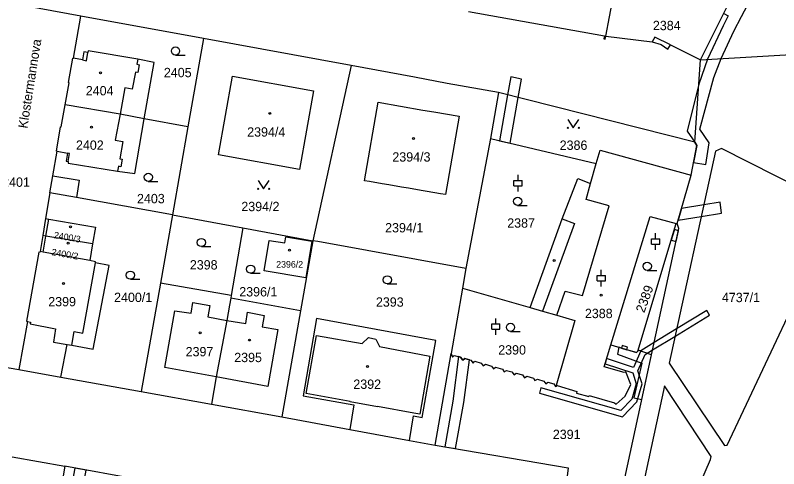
# Model space of a CAD drawing. Extents: x -756746 to -753363, y -1166406 to -1161727.
# Drawn here: x -755962.9 to -755823.6, y -1164823.5 to -1164740.9 of the extents above; entities that cross this region are included whole.
import ezdxf

# ---------------------------------------------------------------- set-up
doc = ezdxf.new("R2010")
doc.units = 0
for name, color, linetype in [('Hranice parcel', 7, 'Continuous'), ('Parcelní čísla', 7, 'Continuous'), ('Pop  PČ popisy', 7, 'Continuous'), ('Vnitřní kresba', 7, 'Continuous'), ('Věcná břemena k části', 7, 'Continuous'), ('Značky budov', 7, 'Continuous'), ('Značky kultur', 7, 'Continuous')]:
    doc.layers.add(name, color=color, linetype=linetype)

msp = doc.modelspace()

# ---------------------------------------------------------------- linework, layer by layer
at = {"layer": 'Hranice parcel'}
for p, q in [((-755855.19, -1164744.66), (-755853.26, -1164734.57)), ((-755950.9, -1164741.05), (-755966.59, -1164738.18)), ((-755837.91, -1164748.96), (-755832.95, -1164739.17)), ((-755952.27, -1164748.71), (-755950.9, -1164741.05)), ((-755928.54, -1164745.07), (-755950.9, -1164741.05)), ((-755928.54, -1164745.07), (-755931.39, -1164761.17)), ((-755901.64, -1164750.02), (-755928.54, -1164745.07)), ((-755837.91, -1164748.96), (-755819.27, -1164747.92)), ((-755838.9, -1164764), (-755837.91, -1164748.96)), ((-755901.64, -1164750.02), (-755908.6, -1164781.97)), ((-755874.74, -1164754.96), (-755876.22, -1164763.34)), ((-755838.9, -1164764), (-755874.74, -1164754.96)), ((-755888.54, -1164758.13), (-755886.52, -1164758.48)), ((-755931.39, -1164761.17), (-755939.37, -1164759.72)), ((-755931.39, -1164761.17), (-755934.2, -1164777.22)), ((-755876.22, -1164763.34), (-755880.7, -1164787.03)), ((-755876.22, -1164763.34), (-755856.91, -1164767.9)), ((-755842.15, -1164778.83), (-755839.59, -1164770)), ((-755956.59, -1164773.21), (-755957.36, -1164777.9)), ((-755957.36, -1164777.9), (-755957.88, -1164780.99)), ((-755934.2, -1164777.22), (-755936.42, -1164789.71)), ((-755934.2, -1164777.22), (-755921.38, -1164779.59)), ((-755921.38, -1164779.59), (-755923.5, -1164791.94)), ((-755921.38, -1164779.59), (-755908.6, -1164781.97)), ((-755842.31, -1164778.79), (-755842.15, -1164778.83)), ((-755957.88, -1164780.99), (-755958.36, -1164783.93)), ((-755948.79, -1164782.53), (-755949.31, -1164785.58)), ((-755908.6, -1164781.97), (-755910.86, -1164794.7)), ((-755880.7, -1164787.03), (-755881.32, -1164790.59)), ((-755936.42, -1164789.71), (-755939.91, -1164809.4)), ((-755923.5, -1164791.94), (-755936.42, -1164789.71)), ((-755881.32, -1164790.59), (-755883.39, -1164802.48)), ((-755881.32, -1164790.59), (-755868.99, -1164794.14)), ((-755923.5, -1164791.94), (-755923.57, -1164792.39)), ((-755910.86, -1164794.7), (-755923.57, -1164792.39)), ((-755910.86, -1164794.7), (-755914.29, -1164814.02)), ((-755977.93, -1164802.62), (-755962.23, -1164805.42)), ((-755886.32, -1164819.18), (-755883.39, -1164802.48)), ((-755962.23, -1164805.42), (-755954.58, -1164806.78)), ((-755954.58, -1164806.78), (-755939.91, -1164809.4)), ((-755939.91, -1164809.4), (-755927.1, -1164811.72)), ((-755927.1, -1164811.72), (-755914.29, -1164814.02)), ((-755914.29, -1164814.02), (-755901.84, -1164816.32)), ((-755901.84, -1164816.32), (-755890.99, -1164818.32)), ((-755890.99, -1164818.32), (-755886.32, -1164819.18)), ((-755963.43, -1164821.33), (-755953.82, -1164823.05)), ((-755940.53, -1164825.47), (-755953.82, -1164823.05))]:
    msp.add_line(p, q, dxfattribs=at)
for points in [[(-755880.19, -1164740.17), (-755855.43, -1164744.63), (-755855.53, -1164745.18), (-755855.29, -1164745.22), (-755855.19, -1164744.66)], [(-755855.19, -1164744.66), (-755846.72, -1164745.69), (-755845.05, -1164746.17), (-755843.84, -1164747.05), (-755843.37, -1164746.27), (-755837.91, -1164748.96)], [(-755939.37, -1164759.72), (-755937.52, -1164749.46), (-755940.54, -1164748.89), (-755949.59, -1164747.36), (-755949.64, -1164747.65), (-755950.39, -1164747.51), (-755950.65, -1164749), (-755952.27, -1164748.71)], [(-755953.8, -1164757.17), (-755953.06, -1164753.15), (-755953.16, -1164753.13), (-755952.37, -1164748.69), (-755952.27, -1164748.71)], [(-755874.74, -1164754.96), (-755884.11, -1164753.28), (-755890.07, -1164752.16), (-755901.64, -1164750.02)], [(-755925.84, -1164766.28), (-755923.24, -1164751.99), (-755908.46, -1164754.66), (-755911.06, -1164768.95), (-755925.84, -1164766.28)], [(-755955.26, -1164765.63), (-755955.36, -1164765.61), (-755954.63, -1164761.18), (-755954.53, -1164761.2), (-755953.8, -1164757.17)], [(-755939.37, -1164759.72), (-755943.78, -1164758.87), (-755953.8, -1164757.17)], [(-755898.27, -1164771.18), (-755899.18, -1164771.02), (-755896.67, -1164756.72), (-755888.54, -1164758.13)], [(-755886.52, -1164758.48), (-755881.94, -1164759.28), (-755884.43, -1164773.54), (-755885.34, -1164773.39)], [(-755955.26, -1164765.63), (-755953.34, -1164765.97), (-755953.58, -1164767.44), (-755953.21, -1164767.5), (-755953.26, -1164767.8), (-755944.21, -1164769.3), (-755941.07, -1164769.68), (-755939.37, -1164759.72)], [(-755839.59, -1164770), (-755838.55, -1164764.59), (-755838.9, -1164764)], [(-755956.59, -1164773.21), (-755956.04, -1164770.1), (-755955.26, -1164765.63)], [(-755856.91, -1164767.9), (-755856.19, -1164765.47), (-755839.59, -1164770)], [(-755813.25, -1164776.36), (-755819.02, -1164772.73), (-755834.09, -1164765.17), (-755835.17, -1164765.65), (-755843.63, -1164804.25), (-755833.54, -1164819.25), (-755833.06, -1164819.2), (-755813.01, -1164776.82), (-755813.25, -1164776.36)], [(-755868.99, -1164794.14), (-755863.14, -1164777.95), (-755860.27, -1164770.61), (-755857.95, -1164771.54), (-755856.91, -1164767.9)], [(-755885.34, -1164773.39), (-755887.74, -1164772.97), (-755888.87, -1164772.78), (-755891.18, -1164772.39), (-755892.43, -1164772.17), (-755894.74, -1164771.78), (-755895.96, -1164771.57), (-755898.27, -1164771.18)], [(-755934.2, -1164777.22), (-755951.72, -1164774.07), (-755956.59, -1164773.21)], [(-755957.36, -1164777.9), (-755956.79, -1164778), (-755948.28, -1164779.49), (-755948.79, -1164782.53)], [(-755854.26, -1164800.92), (-755847.1, -1164777.52), (-755842.31, -1164778.79)], [(-755854.42, -1164837.87), (-755841.84, -1164779.73), (-755842.15, -1164778.83)], [(-755854.26, -1164800.92), (-755849.57, -1164802.34), (-755849.33, -1164802.06), (-755842.31, -1164778.79)], [(-755948.79, -1164782.53), (-755957.3, -1164781.09), (-755957.88, -1164780.99)], [(-755913.72, -1164782.36), (-755913.54, -1164781.26), (-755908.79, -1164782.03), (-755909.87, -1164788.69), (-755917.49, -1164787.46), (-755916.59, -1164781.9), (-755913.72, -1164782.36)], [(-755880.7, -1164787.03), (-755907.67, -1164782.08), (-755908.6, -1164781.97)], [(-755958.36, -1164783.93), (-755958.39, -1164784.08), (-755958.56, -1164784.05), (-755960.86, -1164796.62), (-755960.66, -1164796.65), (-755962.23, -1164805.42)], [(-755949.31, -1164785.58), (-755957.79, -1164784.03), (-755958.36, -1164783.93)], [(-755954.58, -1164806.78), (-755953.42, -1164800.84), (-755952.57, -1164800.98), (-755948.68, -1164801.72), (-755945.75, -1164786.49), (-755948.27, -1164785.98), (-755948.23, -1164785.77), (-755949.31, -1164785.58)], [(-755923.57, -1164792.39), (-755923.79, -1164793.68), (-755924.28, -1164796.47), (-755926.21, -1164806.77), (-755927.1, -1164811.72)], [(-755868.99, -1164794.14), (-755866.73, -1164794.79), (-755864.1, -1164795.54), (-755860.81, -1164796.5), (-755864.2, -1164808.31), (-755864.06, -1164808.35)], [(-755890.99, -1164818.32), (-755890.27, -1164813.84), (-755888.68, -1164814.13), (-755886.19, -1164800.1), (-755907.93, -1164796.09), (-755910.4, -1164810.18), (-755901.15, -1164811.86), (-755901.84, -1164816.32)], [(-755864.06, -1164808.35), (-755860.43, -1164809.44), (-755860.53, -1164809.7), (-755858.28, -1164810.36), (-755858.18, -1164810.12), (-755853.58, -1164811.5), (-755853.27, -1164811.71), (-755851.64, -1164810.26), (-755850.63, -1164808.14), (-755851.54, -1164805.86), (-755851.83, -1164805.98), (-755855.47, -1164804.9), (-755854.26, -1164800.92)], [(-755883.39, -1164802.48), (-755883.14, -1164803.17), (-755882.82, -1164802.84), (-755881.67, -1164803.16), (-755881.26, -1164803.7), (-755880.87, -1164803.39), (-755879.78, -1164803.71), (-755879.38, -1164804.24), (-755879.04, -1164803.92), (-755877.89, -1164804.25), (-755877.52, -1164804.77), (-755877.11, -1164804.47), (-755876.04, -1164804.78), (-755875.64, -1164805.3), (-755875.29, -1164804.99), (-755874.02, -1164805.35), (-755873.73, -1164805.84), (-755873.28, -1164805.57), (-755872.3, -1164805.85), (-755871.88, -1164806.36), (-755871.5, -1164806.08), (-755870.36, -1164806.41), (-755869.97, -1164806.91), (-755869.6, -1164806.63), (-755868.38, -1164806.97), (-755868.12, -1164807.43), (-755867.64, -1164807.18), (-755866.46, -1164807.52), (-755866.11, -1164808), (-755865.75, -1164807.73), (-755864.66, -1164808.03), (-755864.36, -1164808.5), (-755864.06, -1164808.35)], [(-755844.47, -1164808.37), (-755850.96, -1164838.47), (-755850.52, -1164839.05), (-755844.7, -1164840.28), (-755843.86, -1164839.76), (-755836.08, -1164821.84), (-755835.96, -1164821.24), (-755844.47, -1164808.37)], [(-755886.32, -1164819.18), (-755862.03, -1164823.3), (-755863.62, -1164836.28), (-755854.42, -1164837.87)], [(-755953.82, -1164823.05), (-755956.26, -1164837.13), (-755958.7, -1164851.23), (-755959.1, -1164853.41), (-755963.89, -1164852.55)]]:
    msp.add_lwpolyline(points, dxfattribs=at)
at = {"layer": 'Vnitřní kresba'}
for p, q in [((-755846.24, -1164744.87), (-755846.72, -1164745.69)), ((-755843.37, -1164746.27), (-755846.24, -1164744.87)), ((-755949.89, -1164749.14), (-755949.64, -1164747.65)), ((-755950.65, -1164749), (-755949.89, -1164749.14)), ((-755940.54, -1164748.89), (-755940.71, -1164749.8)), ((-755940.71, -1164749.8), (-755940.26, -1164749.89)), ((-755940.26, -1164749.89), (-755940.52, -1164751.3)), ((-755940.97, -1164751.22), (-755941.54, -1164754.34)), ((-755940.52, -1164751.3), (-755940.97, -1164751.22)), ((-755942.93, -1164754.08), (-755943.78, -1164758.87)), ((-755941.54, -1164754.34), (-755942.93, -1164754.08)), ((-755943.78, -1164758.87), (-755944.64, -1164763.63)), ((-755944.64, -1164763.63), (-755943.27, -1164763.87)), ((-755943.27, -1164763.87), (-755943.81, -1164767.01)), ((-755952.97, -1164766.03), (-755953.34, -1164765.97)), ((-755953.21, -1164767.5), (-755952.97, -1164766.03)), ((-755943.81, -1164767.01), (-755943.37, -1164767.09)), ((-755943.37, -1164767.09), (-755943.6, -1164768.46)), ((-755944.05, -1164768.38), (-755944.21, -1164769.3)), ((-755943.6, -1164768.46), (-755944.05, -1164768.38)), ((-755956.04, -1164770.1), (-755951.21, -1164770.9)), ((-755951.21, -1164770.9), (-755951.72, -1164774.07)), ((-755858.78, -1164774.42), (-755857.95, -1164771.54)), ((-755859.44, -1164791.94), (-755854.55, -1164775.6)), ((-755854.55, -1164775.6), (-755858.78, -1164774.42)), ((-755957.3, -1164781.09), (-755956.79, -1164778)), ((-755863.14, -1164777.95), (-755860.86, -1164778.81)), ((-755860.86, -1164778.81), (-755866.73, -1164794.79)), ((-755957.79, -1164784.03), (-755957.3, -1164781.09)), ((-755950.59, -1164798.77), (-755948.27, -1164785.98)), ((-755864.1, -1164795.54), (-755862.61, -1164791.15)), ((-755862.61, -1164791.15), (-755859.44, -1164791.94)), ((-755930.81, -1164795.12), (-755930.52, -1164793.22)), ((-755930.52, -1164793.22), (-755927.37, -1164793.76)), ((-755927.37, -1164793.76), (-755927.75, -1164795.81)), ((-755935.59, -1164805.07), (-755933.75, -1164794.71)), ((-755933.75, -1164794.71), (-755930.81, -1164795.12)), ((-755920.85, -1164797), (-755920.54, -1164794.98)), ((-755920.54, -1164794.98), (-755917.48, -1164795.57)), ((-755960.66, -1164796.65), (-755960.08, -1164796.77)), ((-755927.75, -1164795.81), (-755924.28, -1164796.47)), ((-755924.28, -1164796.47), (-755920.85, -1164797)), ((-755917.48, -1164795.57), (-755917.82, -1164797.61)), ((-755960.08, -1164796.77), (-755960.15, -1164797.09)), ((-755960.15, -1164797.09), (-755955.57, -1164798)), ((-755955.57, -1164798), (-755955.92, -1164800.43)), ((-755917.82, -1164797.61), (-755914.97, -1164798.11)), ((-755952.57, -1164800.98), (-755952.12, -1164798.5)), ((-755952.12, -1164798.5), (-755950.59, -1164798.77)), ((-755914.97, -1164798.11), (-755916.82, -1164808.49)), ((-755909.82, -1164809.77), (-755907.96, -1164799.21)), ((-755907.96, -1164799.21), (-755899.58, -1164800.69)), ((-755955.92, -1164800.43), (-755953.42, -1164800.84)), ((-755899.58, -1164800.69), (-755898.47, -1164799.58)), ((-755898.47, -1164799.58), (-755897.12, -1164799.88)), ((-755897.12, -1164799.88), (-755896.47, -1164801.24)), ((-755896.47, -1164801.24), (-755887.24, -1164802.98)), ((-755887.24, -1164802.98), (-755889.09, -1164813.54)), ((-755926.21, -1164806.77), (-755935.59, -1164805.07)), ((-755916.82, -1164808.49), (-755926.21, -1164806.77)), ((-755901.79, -1164811.23), (-755909.82, -1164809.77)), ((-755901.81, -1164811.33), (-755901.79, -1164811.23)), ((-755896.82, -1164812.24), (-755901.81, -1164811.33)), ((-755896.8, -1164812.14), (-755896.82, -1164812.24)), ((-755890.18, -1164813.34), (-755896.8, -1164812.14)), ((-755889.09, -1164813.54), (-755890.18, -1164813.34))]:
    msp.add_line(p, q, dxfattribs=at)
at = {"layer": 'Věcná břemena k části'}
msp.add_lwpolyline([(-755833.66, -1164740.56), (-755832.83, -1164740.99), (-755833.78, -1164742.79), (-755836.6, -1164748.89), (-755838.2, -1164753.42), (-755840.33, -1164761.99), (-755838.9, -1164764), (-755838.55, -1164764.59), (-755839.15, -1164767.72), (-755836.93, -1164768.08), (-755836.3, -1164764.13), (-755837.99, -1164761.61), (-755835.49, -1164752.23), (-755834.15, -1164748.75), (-755831.84, -1164743.75), (-755830.43, -1164741.07), (-755828.16, -1164736.77)], dxfattribs=at)
for points in [[(-755872.49, -1164752.07), (-755873.09, -1164755.38), (-755874.57, -1164763.73), (-755872.62, -1164764.19), (-755871.15, -1164755.87), (-755870.54, -1164752.5)], [(-755841.35, -1164776.08), (-755841.97, -1164778.21), (-755837.77, -1164777.52), (-755834.07, -1164776.93), (-755834.3, -1164774.94), (-755837.31, -1164775.42)], [(-755842.65, -1164779.92), (-755843.23, -1164781.84), (-755842.35, -1164782.1), (-755841.93, -1164780.14)], [(-755836.76, -1164794.68), (-755842.27, -1164798.03), (-755846.34, -1164800.51), (-755848.78, -1164802), (-755850.11, -1164805.02), (-755855.02, -1164803.41), (-755855.31, -1164804.37), (-755850.23, -1164806.04), (-755849.6, -1164808.02), (-755850.42, -1164810.79), (-755852.43, -1164812.89), (-755866.99, -1164808.77), (-755867.26, -1164809.74), (-755852.13, -1164814.01), (-755849.52, -1164811.31), (-755848.56, -1164808), (-755849.3, -1164805.67), (-755848, -1164802.68), (-755846.63, -1164801.85), (-755842.56, -1164799.38), (-755836.25, -1164795.54)], [(-755852.79, -1164801.37), (-755853.04, -1164802.62), (-755848.59, -1164804.24), (-755850.07, -1164810.55), (-755848.58, -1164810.9), (-755846.82, -1164802.74), (-755849.27, -1164801.86), (-755849.33, -1164802.06), (-755849.57, -1164802.34), (-755851.36, -1164801.8), (-755852.32, -1164801.51)], [(-755852.32, -1164801.51), (-755851.36, -1164801.8), (-755851.21, -1164801.32), (-755852.17, -1164801.03)], [(-755882.01, -1164803.07), (-755883.06, -1164811.17), (-755884.56, -1164819.48), (-755882.59, -1164819.81), (-755881.08, -1164811.45), (-755880.06, -1164803.63), (-755880.87, -1164803.39), (-755881.26, -1164803.7), (-755881.67, -1164803.16)], [(-755949.95, -1164823.75), (-755952.04, -1164823.37), (-755953.46, -1164831.11), (-755955.16, -1164830.79), (-755955.51, -1164832.82), (-755953.84, -1164833.14), (-755956.06, -1164844.74), (-755957.53, -1164844.49), (-755957.88, -1164846.52), (-755954.36, -1164847.12), (-755951.56, -1164832.52)]]:
    msp.add_lwpolyline(points, close=True, dxfattribs=at)
at = {"layer": 'Značky budov'}
for centre in [(-755947.33, -1164751.36), (-755916.47, -1164758.74), (-755949, -1164761.27), (-755890.25, -1164763.31), (-755952.83, -1164779.41), (-755953.24, -1164782.39), (-755912.87, -1164783.68), (-755864.58, -1164785.53), (-755954.08, -1164789.74), (-755856.03, -1164791.85), (-755929.18, -1164798.73), (-755920.14, -1164800.04), (-755898.64, -1164804.86)]:
    msp.add_circle(centre, 0.175, dxfattribs=at)
at = {"layer": 'Značky kultur'}
for p, q in [((-755933.65, -1164748.12), (-755931.9, -1164748.12)), ((-755871.17, -1164770.97), (-755871.17, -1164769.97)), ((-755938.62, -1164771.13), (-755936.87, -1164771.13)), ((-755871.92, -1164770.97), (-755870.42, -1164770.97)), ((-755871.92, -1164771.97), (-755871.92, -1164770.97)), ((-755870.42, -1164771.97), (-755870.42, -1164770.97)), ((-755871.92, -1164771.97), (-755870.42, -1164771.97)), ((-755871.17, -1164772.97), (-755871.17, -1164771.97)), ((-755871.25, -1164775.51), (-755869.5, -1164775.51)), ((-755846.08, -1164781.6), (-755846.08, -1164780.6)), ((-755846.83, -1164781.6), (-755845.33, -1164781.6)), ((-755846.83, -1164782.6), (-755846.83, -1164781.6)), ((-755846.83, -1164782.6), (-755845.33, -1164782.6)), ((-755846.08, -1164783.6), (-755846.08, -1164782.6)), ((-755845.33, -1164782.6), (-755845.33, -1164781.6)), ((-755928.94, -1164783.02), (-755927.19, -1164783.02)), ((-755919.95, -1164787.88), (-755918.2, -1164787.88)), ((-755856.75, -1164788.28), (-755855.25, -1164788.28)), ((-755856.75, -1164789.28), (-755856.75, -1164788.28)), ((-755856, -1164788.28), (-755856, -1164787.28)), ((-755855.25, -1164789.28), (-755855.25, -1164788.28)), ((-755847.61, -1164787.35), (-755845.86, -1164787.35)), ((-755941.89, -1164788.98), (-755940.14, -1164788.98)), ((-755856.75, -1164789.28), (-755855.25, -1164789.28)), ((-755856, -1164790.28), (-755856, -1164789.28)), ((-755895.02, -1164789.82), (-755893.27, -1164789.82)), ((-755875.22, -1164797.09), (-755875.22, -1164796.09)), ((-755875.97, -1164797.09), (-755874.47, -1164797.09)), ((-755875.97, -1164798.09), (-755875.97, -1164797.09)), ((-755874.47, -1164798.09), (-755874.47, -1164797.09)), ((-755875.97, -1164798.09), (-755874.47, -1164798.09)), ((-755875.22, -1164799.09), (-755875.22, -1164798.09)), ((-755872.55, -1164798.47), (-755870.8, -1164798.47))]:
    msp.add_line(p, q, dxfattribs=at)
for points in [[(-755862.1, -1164759.88), (-755861.1, -1164761.38), (-755860.1, -1164759.88)], [(-755918.58, -1164771), (-755917.58, -1164772.5), (-755916.58, -1164771)]]:
    msp.add_lwpolyline(points, dxfattribs=at)
for centre, radius in [((-755933.65, -1164747.37), 0.75), ((-755862.1, -1164761.38), 0.1), ((-755860.1, -1164761.38), 0.1), ((-755938.62, -1164770.38), 0.75), ((-755918.58, -1164772.5), 0.1), ((-755916.58, -1164772.5), 0.1), ((-755871.25, -1164774.76), 0.75), ((-755928.94, -1164782.27), 0.75), ((-755919.95, -1164787.13), 0.75), ((-755847.61, -1164786.6), 0.75), ((-755941.89, -1164788.23), 0.75), ((-755895.02, -1164789.07), 0.75), ((-755872.55, -1164797.72), 0.75)]:
    msp.add_circle(centre, radius, dxfattribs=at)

# ---------------------------------------------------------------- texts
at = {"layer": 'Parcelní čísla'}
for s, height, p in [('2384', 1.7, (-755846.58, -1164743.58)), ('2405', 1.7, (-755935.78, -1164752.15)), ('2404', 1.7, (-755950.02, -1164755.46)), ('2394/4', 1.7, (-755920.58, -1164762.98)), ('2402', 1.7, (-755951.81, -1164765.38)), ('2386', 1.7, (-755863.58, -1164765.39)), ('2394/3', 1.7, (-755894.1, -1164767.53)), ('2401', 1.7, (-755965.28, -1164772.12)), ('2403', 1.7, (-755940.68, -1164775.12)), ('2394/2', 1.7, (-755921.65, -1164776.56)), ('2387', 1.7, (-755873.15, -1164779.57)), ('2394/1', 1.7, (-755895.42, -1164780.43)), ('2398', 1.7, (-755931.04, -1164787.19)), ('2396/2', 1.2, (-755915.29, -1164786.85)), ('2396/1', 1.7, (-755922.03, -1164792.1)), ('2399', 1.7, (-755956.87, -1164793.9)), ('2400/1', 1.7, (-755944.86, -1164793.11)), ('2393', 1.7, (-755897.1, -1164793.97)), ('4737/1', 1.7, (-755833.99, -1164793.14)), ('2388', 1.7, (-755858.98, -1164796.05)), ('2397', 1.7, (-755931.81, -1164803.01)), ('2390', 1.7, (-755874.79, -1164802.69)), ('2395', 1.7, (-755922.95, -1164804.07)), ('2392', 1.7, (-755901.22, -1164808.94)), ('2391', 1.7, (-755864.83, -1164818.08))]:
    msp.add_text(s, height=height, dxfattribs=at).set_placement(p)
for s, height, rotation, p in [('2400/3', 1.2, 350, (-755955.92, -1164781.46)), ('2400/2', 1.2, 350, (-755956.35, -1164784.55)), ('2389', 1.7, 70, (-755848.16, -1164795.2))]:
    msp.add_text(s, height=height, rotation=rotation, dxfattribs=at).set_placement(p)
at = {"layer": 'Pop  PČ popisy'}
msp.add_text('Klostermannova', height=1.7, rotation=81, dxfattribs=at).set_placement((-755960.69, -1164761.57))

doc.saveas('drawing.dxf')
